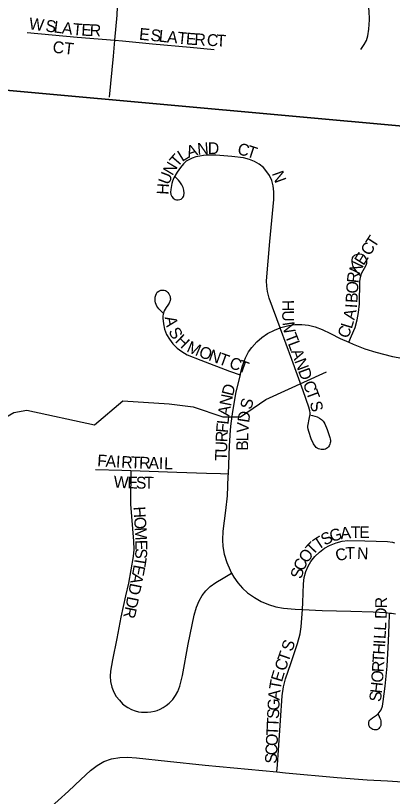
# Model space of a CAD drawing. Extents: x 1410790 to 1770854, y 448063 to 770588.
# Drawn here: x 1547506 to 1549100, y 630526 to 633827 of the extents above; entities that cross this region are included whole.
import ezdxf

# ---------------------------------------------------------------- set-up
doc = ezdxf.new("R2010")
doc.units = 0
for name, color, linetype in [('GM_X_Minor_River', 7, 'Continuous'), ('GM_X_Section', 7, 'Continuous'), ('GM_X_Township_Road', 7, 'Continuous'), ('GM_X_Township_Subdivision', 7, 'Continuous'), ('GM_X_Township_Subdivision_Text', 7, 'Continuous')]:
    doc.layers.add(name, color=color, linetype=linetype)

msp = doc.modelspace()

# ---------------------------------------------------------------- linework, layer by layer
at = {"layer": 'GM_X_Minor_River'}
msp.add_lwpolyline([(1546608.2, 631388.7), (1546727.1, 631426.8), (1546785.1, 631417.8), (1546896.2, 631466), (1547159.2, 631726.2), (1547279.9, 631984.7), (1547319, 632044.2), (1547499.2, 632149.4), (1547553.5, 632158.5), (1547839.2, 632097.4), (1547959.1, 632197.7), (1548155.4, 632186.3), (1548257.4, 632172.5), (1548383, 632130.2), (1548457.2, 632131), (1548564.7, 632203.3), (1548821.3, 632321.2)], dxfattribs=at)
at = {"layer": 'GM_X_Section'}
for points in [[(1550230.3, 638666.5), (1549719.6, 633308.3), (1544399.7, 633789.9), (1544904.4, 639125.6)], [(1544399.7, 633789.9), (1549719.6, 633308.3), (1549189.3, 627980.4), (1543911.7, 628488)]]:
    msp.add_lwpolyline(points, close=True, dxfattribs=at)
at = {"layer": 'GM_X_Township_Road'}
for points in [[(1547505.6, 630342.1), (1547524.9, 630360), (1547546.2, 630380.2), (1547580.6, 630410.5), (1547602.1, 630430.6), (1547642.4, 630468.5), (1547729.7, 630547.9), (1547782.4, 630597.3), (1547823.6, 630634.5), (1547851.7, 630656.2), (1547878.9, 630672.7), (1547912, 630684.4), (1547946.9, 630689.8), (1547979.2, 630691.2), (1548018.2, 630688.7), (1548148.5, 630674.8), (1548308.5, 630657.9), (1548550.2, 630634.8), (1548610.9, 630629.1)], [(1548610.9, 630629.1), (1548648.1, 630625.6), (1548865.9, 630605.1), (1548992.9, 630596.1), (1549079.3, 630590.8), (1549183.8, 630584.4), (1549297.3, 630578.1), (1549312.4, 630577.3)]]:
    msp.add_lwpolyline(points, dxfattribs=at)
at = {"layer": 'GM_X_Township_Subdivision'}
for points in [[(1547926.1, 633723.2), (1547935.6, 633828.9), (1547936.7, 633864.9), (1547934.6, 633900.9), (1547927.8, 633942.9), (1547902.1, 634064.9), (1547875.4, 634196.6), (1547835.2, 634385.9), (1547815.9, 634475.6), (1547805.7, 634537), (1547799.7, 634592.3), (1547798, 634638.1), (1547799.7, 634683.9), (1547806.6, 634749.1), (1547809.7, 634776.1)], [(1548965.9, 633683.3), (1548980.5, 633705.1), (1548989.7, 633722.4), (1548995.6, 633741.1), (1549000.2, 633770.2), (1549002.3, 633809.4), (1549000.9, 633848.7), (1548996.2, 633881.1), (1548987.9, 633912.8), (1548977.2, 633940.3), (1548962, 633969.2), (1548820.5, 634189.7), (1548744.1, 634308), (1548655.5, 634449.6), (1548638.3, 634481.3), (1548628.4, 634505.6), (1548621.4, 634530.8), (1548617.1, 634559.9), (1548616.2, 634595.9), (1548621, 634667.9), (1548623.3, 634703.7)], [(1547555.2, 633755.5), (1547767.2, 633735.9), (1547926.1, 633723.2)], [(1547903.7, 633482.8), (1547920.1, 633655.8), (1547926.1, 633723.2)], [(1547926.1, 633723.2), (1547958, 633720.2), (1548084.8, 633708.3), (1548244.1, 633693.8), (1548346.5, 633684.6)], [(1548624.7, 632506.7), (1548578.5, 632631.9), (1548570.9, 632660.4), (1548568, 632683.1), (1548567.8, 632706), (1548582, 632872.7), (1548598.4, 633049.1), (1548598.8, 633081.9), (1548595.7, 633108), (1548589.7, 633130.1), (1548580.1, 633150.9), (1548569.2, 633167.3), (1548553.9, 633184.4), (1548536.2, 633199), (1548516.4, 633210.6), (1548495.1, 633219.2), (1548469.7, 633225.4), (1548420.9, 633231.8), (1548353.3, 633236.9), (1548333.4, 633237.1), (1548313.6, 633236.6), (1548300.4, 633235.3), (1548285.5, 633233.4), (1548269, 633229.6), (1548253.5, 633225.1), (1548244, 633220.8), (1548235.4, 633216.2), (1548227.7, 633211.1), (1548216, 633200.7), (1548203.3, 633184.8), (1548189.9, 633165.2), (1548175.7, 633141.4), (1548170.2, 633126.9), (1548167.3, 633117.2), (1548163.7, 633100.7), (1548162.3, 633091.3), (1548161.7, 633080.9), (1548162.9, 633071.2), (1548166.6, 633062.2), (1548172.9, 633054.9), (1548181.3, 633050), (1548187, 633048.3), (1548193.8, 633048.1), (1548200.7, 633049.3), (1548206.8, 633051.7), (1548213.9, 633058.2), (1548216.7, 633062.5), (1548218.2, 633066.8), (1548219.3, 633076.4), (1548217.5, 633089.5), (1548214.2, 633100.6), (1548209.7, 633111), (1548201, 633124.4), (1548194.8, 633132.1), (1548182.7, 633144.2), (1548180.6, 633146.1)], [(1548915.4, 632446), (1548926.6, 632472.8), (1548941.7, 632508.9), (1548951, 632540.2), (1548956.9, 632572.3), (1548959.9, 632608.1), (1548961.4, 632702.7), (1548964.3, 632721.9), (1548969.6, 632737.3), (1548988.3, 632771.7), (1548990, 632776.2), (1548990.9, 632781), (1548991.4, 632786.2), (1548991.1, 632790.8), (1548990, 632796.4), (1548988.5, 632800.1), (1548985.8, 632804.7), (1548983.2, 632808.3), (1548979.6, 632811.7), (1548975.6, 632814.4), (1548970.1, 632817), (1548962, 632818.6), (1548956.3, 632818.5), (1548951.1, 632817.7), (1548946.1, 632816.1), (1548941.4, 632814.1), (1548937.9, 632812.1), (1548935, 632809.9), (1548932.6, 632807.3), (1548930.2, 632802.7), (1548929, 632799.2), (1548928.2, 632795.4), (1548928, 632790.8), (1548928, 632785.9), (1548929, 632778.2), (1548930.8, 632771.6), (1548932.6, 632766.5), (1548935, 632761.5), (1548939.2, 632755.1), (1548945.8, 632746.2), (1548961.4, 632730.4), (1548964.3, 632728)], [(1548129.5, 632570.9), (1548123.9, 632575.5), (1548118.5, 632580.5), (1548112.3, 632586.9), (1548107.4, 632593.2), (1548103.9, 632599.1), (1548101, 632605.5), (1548098.4, 632612.5), (1548097, 632619.6), (1548096.1, 632627.8), (1548096.8, 632636.5), (1548098.9, 632645.2), (1548102, 632652.5), (1548105.6, 632657.7), (1548112.1, 632662.7), (1548120, 632665.6), (1548127.7, 632666.6), (1548134.2, 632666.1), (1548140.5, 632664.3), (1548145, 632661.7), (1548149.7, 632656.7), (1548154, 632651.1), (1548157.1, 632645.5), (1548159.4, 632640), (1548160.2, 632634.4), (1548160.6, 632629.9), (1548159.7, 632622.8), (1548156, 632611.9), (1548150.4, 632602.9), (1548143.2, 632593.4), (1548134.4, 632578.4), (1548130.2, 632565.1), (1548129, 632556.3), (1548128.8, 632547.9), (1548131.1, 632524.2), (1548136.5, 632501.2), (1548144.9, 632479), (1548156.4, 632458.4), (1548170.6, 632439.5), (1548189.7, 632420.5), (1548208.6, 632406.3), (1548232.1, 632393.4), (1548290.2, 632370), (1548410.4, 632323.8), (1548455.8, 632308.5)], [(1548624.7, 632506.7), (1548627.6, 632507.8), (1548661.8, 632517.3), (1548687.1, 632521.1), (1548716, 632521.3), (1548744.7, 632518), (1548772.9, 632511.3), (1548803.3, 632500.4), (1548838.4, 632483.5), (1548879.4, 632462.5), (1548915.4, 632446)], [(1548455.8, 632308.5), (1548465.7, 632346.3), (1548478.4, 632379.5), (1548491.7, 632405.2), (1548504.6, 632423.4), (1548526.1, 632447.4), (1548547.9, 632466.4), (1548571.8, 632482.7), (1548600.4, 632497.4), (1548624.7, 632506.7)], [(1548754.1, 632138), (1548761.6, 632136.4), (1548771.3, 632133.9), (1548781.5, 632130.3), (1548790.9, 632124.7), (1548799.4, 632119.3), (1548806.4, 632112.4), (1548809.9, 632107.7), (1548813.6, 632101.5), (1548823.8, 632077.4), (1548835.3, 632042.9), (1548836.8, 632037.1), (1548837.3, 632029.9), (1548837.5, 632025.5), (1548836.6, 632020.2), (1548835.6, 632014.6), (1548832.4, 632008.7), (1548829, 632003.7), (1548825.2, 631999.5), (1548820.5, 631996.9), (1548816.4, 631994.4), (1548811.5, 631993.1), (1548805.5, 631992), (1548798.4, 631992.3), (1548792.1, 631993.7), (1548787.3, 631995.4), (1548781.9, 631997.9), (1548777.6, 632001), (1548772.7, 632006.6), (1548765.9, 632017.2), (1548756.4, 632038.2), (1548745.6, 632069.3), (1548743.4, 632078.1), (1548742.7, 632085.3), (1548742.2, 632091.7), (1548742.8, 632098.3), (1548747.6, 632120.8), (1548750.7, 632134.9), (1548751.3, 632140), (1548751.6, 632148.2), (1548750.6, 632156.3), (1548746.9, 632172.2), (1548722.4, 632240.1), (1548673.7, 632372.5), (1548626.3, 632502.1), (1548624.7, 632506.7)], [(1548915.4, 632446), (1548933.4, 632437.7), (1548982.6, 632418.5), (1549029.9, 632403.9), (1549100.3, 632386.2), (1549155.3, 632375.7), (1549280.4, 632354.9)], [(1548455.8, 632308.5), (1548438.1, 632235.8), (1548423.2, 632153.9), (1548416.9, 632101.8), (1548413.4, 632075.8), (1548409, 632007), (1548404.6, 631889.2)], [(1547844.4, 631907.6), (1547956, 631905.5), (1547993.5, 631904.2)], [(1547993.5, 631904.2), (1547992.9, 631873.1), (1547991.5, 631804.2), (1547991.6, 631761.3), (1548005.5, 631604.6), (1548005.9, 631569), (1548003.1, 631540.2), (1547983.2, 631427.8), (1547970.3, 631373.4), (1547951.8, 631283.4), (1547933.8, 631193.5), (1547915.8, 631103.6), (1547906.9, 631054.8), (1547905.6, 631034.6), (1547907.5, 631011), (1547913, 630988), (1547921.8, 630966), (1547932.1, 630948.3), (1547945, 630932.5), (1547958.6, 630917.6), (1547969.2, 630909.1), (1547981.3, 630901.4), (1547996.9, 630893), (1548012.4, 630887.2), (1548025.8, 630883.6), (1548038.1, 630881.8), (1548051.9, 630881.4), (1548063.6, 630881.3), (1548077.5, 630882.8), (1548093.8, 630885.8), (1548105.4, 630889.4), (1548116.9, 630894.4), (1548130.2, 630901.4), (1548143.4, 630910.2), (1548155.9, 630920.1), (1548170.5, 630935.5), (1548182.8, 630951.8), (1548192.5, 630969.8), (1548200.7, 630991.9), (1548211.6, 631037), (1548236.6, 631169.6), (1548261.7, 631291.7), (1548271.1, 631326), (1548282.3, 631352.7), (1548295.2, 631374.9), (1548310.9, 631395), (1548329.2, 631412.9), (1548352.4, 631430.2), (1548383.4, 631448.1), (1548419.8, 631469.1)], [(1547993.5, 631904.2), (1548188.6, 631897.3), (1548313.1, 631892.8), (1548372.1, 631890.5), (1548404.6, 631889.2)], [(1548404.6, 631889.2), (1548404.3, 631879.1), (1548400.7, 631797.2), (1548393.9, 631735.2), (1548382.6, 631647.3), (1548381, 631611.2), (1548382.8, 631581.7), (1548388.6, 631549.4), (1548398.9, 631514.8), (1548412.9, 631481.6), (1548419.8, 631469.1)], [(1548719.1, 631315.8), (1548720.2, 631345.4), (1548723.3, 631424.4), (1548727, 631451), (1548734, 631477), (1548743.3, 631498.8), (1548755.3, 631519.1), (1548772, 631540.3), (1548791.3, 631559.1), (1548812.8, 631575.4), (1548833.4, 631586.8), (1548861.5, 631597.9), (1548887.6, 631604.8), (1548911.1, 631607.6), (1548983.7, 631606.3), (1549079.3, 631603.4), (1549099.4, 631600.7), (1549108, 631598.4)], [(1548419.8, 631469.1), (1548428.8, 631452.9), (1548445.7, 631428.7), (1548465.3, 631406.5), (1548487.4, 631387), (1548516.9, 631366.1), (1548545.3, 631349.8), (1548575.4, 631336.6), (1548606.7, 631327.1), (1548639, 631321.1), (1548688, 631317.1), (1548719.1, 631315.8)], [(1548610.9, 630629.1), (1548613.3, 630659.7), (1548618.2, 630721.8), (1548626.6, 630845.9), (1548634.2, 630950.2), (1548639.6, 630988.6), (1548648.1, 631023.2), (1548669.7, 631088.1), (1548698.6, 631172), (1548709.8, 631213.5), (1548714.4, 631243.1), (1548719.1, 631315.8)], [(1548719.1, 631315.8), (1548802.7, 631312.4), (1548924, 631309.1), (1549018.9, 631306.3), (1549070.4, 631302.7), (1549088.2, 631300.8)], [(1549039.7, 630873.7), (1549044, 630863.8), (1549047.2, 630856.3), (1549048.9, 630850.5), (1549050.2, 630845.3), (1549051.1, 630836), (1549050.8, 630829.7), (1549050.2, 630825.2), (1549048.3, 630820.2), (1549045.8, 630816.4), (1549042.7, 630813.1), (1549039.7, 630810.6), (1549037.1, 630809.1), (1549033.7, 630807.8), (1549029.2, 630807), (1549026.3, 630806.8), (1549022.2, 630807.3), (1549017.4, 630808.6), (1549012.6, 630810.9), (1549008.1, 630814.1), (1549004.7, 630817.3), (1549002.4, 630820.8), (1549001.1, 630823.6), (1549000, 630826.6), (1548999.4, 630831), (1548999.4, 630835.2), (1549000.2, 630841.2), (1549001.2, 630844.2), (1549003, 630847.5), (1549005.2, 630850.1), (1549008, 630852.5), (1549015.4, 630857.9), (1549032.3, 630869.6), (1549039.4, 630875.2), (1549044.2, 630880.8), (1549051.5, 630891.7), (1549057.5, 630906.9), (1549061.2, 630926.3), (1549068.9, 630991.7), (1549077.8, 631076.6), (1549083.1, 631181.6), (1549086.1, 631252.7), (1549088, 631294.6), (1549088.2, 631300.8)], [(1549088.2, 631300.8), (1549095.9, 631300), (1549112.5, 631298)]]:
    msp.add_lwpolyline(points, dxfattribs=at)

# ---------------------------------------------------------------- texts
at = {"layer": 'GM_X_Township_Subdivision_Text'}
for s, rotation, p in [('W', 352.7686, (1547560.6, 633769.7)), ('S', 352.769, (1547630.5, 633760.8)), ('L', 352.769, (1547665.4, 633756.4)), ('A', 352.7678, (1547700.3, 633751.9)), ('T', 354.7574, (1547745.8, 633746.2)), ('E', 357.2145, (1547783.2, 633742.8)), ('R', 357.5104, (1547818.7, 633741.1)), ('E', 354.3084, (1548026.8, 633725.7)), ('S', 354.3253, (1548074.9, 633720.9)), ('L', 354.3084, (1548110, 633717.4)), ('A', 354.3068, (1548145, 633713.9)), ('T', 354.3084, (1548188.8, 633709.6)), ('E', 355.3171, (1548224.8, 633706)), ('R', 356.6654, (1548261.1, 633703)), ('C', 356.8202, (1548314, 633700)), ('T', 356.8357, (1548353.5, 633697.8)), ('CT', 353.6625, (1547661, 633671)), ('A', 18.276, (1548237.5, 633225)), ('N', 4.5077, (1548276.2, 633238.1)), ('D', 0.306, (1548319.1, 633241.5)), ('C', 346.5411, (1548441.4, 633241.6)), ('T', 342.17, (1548479, 633232.6)), ('T', 49.292, (1548190.5, 633183.7)), ('L', 31.6057, (1548210.3, 633207.8)), ('N', 59.1, (1548169.2, 633147.8)), ('N', 289.8038, (1548589.3, 633160.2)), ('U', 69.2214, (1548154.6, 633108.8)), ('H', 86.545, (1548152.8, 633068.8)), ('T', 57.1663, (1549024.9, 632841.6)), ('C', 57.176, (1549003.4, 632808.3)), ('E', 57.424, (1548977.3, 632767.6)), ('N', 64.6081, (1548959.3, 632729.3)), ('R', 83.8448, (1548956.2, 632694.2)), ('O', 86.5473, (1548953.6, 632650.9)), ('B', 86.2812, (1548951.1, 632611.1)), ('H', 270.2405, (1548633.7, 632625.1)), ('A', 77.2953, (1548938.8, 632537.6)), ('I', 86.4608, (1548949.7, 632589.2)), ('A', 281.1728, (1548136.4, 632551.5)), ('U', 270.252, (1548633.8, 632581.1)), ('N', 278.4095, (1548634.6, 632529.3)), ('C', 67.892, (1548911, 632458.7)), ('L', 73.1987, (1548927.6, 632500.2)), ('S', 299.2804, (1548150.9, 632492.2)), ('H', 316.1625, (1548177.9, 632448.8)), ('T', 291.2727, (1548644.2, 632474)), ('M', 336.9329, (1548226.1, 632407.5)), ('L', 290.4313, (1548656.9, 632441.4)), ('O', 340.0333, (1548277.4, 632385.7)), ('N', 340.0903, (1548318.8, 632370.7)), ('T', 340.0706, (1548360.2, 632355.7)), ('C', 340.0957, (1548405.7, 632339.2)), ('A', 290.4051, (1548669.2, 632408.4)), ('N', 290.4232, (1548684.5, 632367.2)), ('T', 340.1253, (1548442.9, 632325.7)), ('D', 290.4051, (1548699.9, 632325.9)), ('C', 290.4168, (1548719.8, 632272.3)), ('D', 76.2765, (1548425.4, 632216.1)), ('T', 290.4251, (1548733.7, 632235.2)), ('N', 78.4029, (1548416.6, 632173.5)), ('S', 75.5331, (1548502.7, 632158.9)), ('S', 283.6785, (1548749.7, 632191.1)), ('A', 81.1342, (1548410, 632130.7)), ('D', 81.2887, (1548493.3, 632103.8)), ('L', 83.702, (1548406.2, 632096.3)), ('F', 85.2681, (1548403.3, 632061.6)), ('V', 85.8209, (1548490.2, 632061)), ('R', 87.9355, (1548401.9, 632022.6)), ('L', 89.0711, (1548489.7, 632026.5)), ('U', 88.0326, (1548400.4, 631978.6)), ('B', 89.9271, (1548489.6, 631987.1)), ('T', 88.0599, (1548399.2, 631943.5)), ('F', 356.5549, (1547850.4, 631921.8)), ('A', 356.545, (1547885.5, 631919.6)), ('I', 356.5437, (1547929.5, 631917)), ('R', 356.8075, (1547951.7, 631915.6)), ('T', 358.0217, (1547992.4, 631913.4)), ('R', 358.5449, (1548028, 631912.1)), ('A', 358.5741, (1548067.7, 631911.1)), ('I', 358.557, (1548111.6, 631910.1)), ('L', 358.5746, (1548133.7, 631909.5)), ('W', 356.9218, (1547920, 631831.5)), ('E', 358.4501, (1547978.5, 631828.4)), ('S', 359.3543, (1548014.6, 631827.4)), ('T', 359.9208, (1548050.3, 631827)), ('H', 273.3459, (1548004.4, 631750.2)), ('O', 273.3241, (1548007, 631706.2)), ('M', 273.3318, (1548009.5, 631662.3)), ('G', 16.8311, (1548842.2, 631600.8)), ('A', 5.9781, (1548881.8, 631613.1)), ('T', 0.9289, (1548924.4, 631617.6)), ('E', 0, (1548959.4, 631618.2)), ('T', 33.1521, (1548785.4, 631566)), ('S', 29.1077, (1548814, 631584.8)), ('E', 270.9835, (1548012.6, 631610.1)), ('T', 46.4104, (1548763.4, 631542.5)), ('S', 267.978, (1548013.2, 631575.6)), ('O', 53.4536, (1548738.3, 631508.4)), ('C', 18.2507, (1548867.9, 631517.5)), ('T', 1.6124, (1548901.8, 631529.3)), ('N', 357.6823, (1548949.3, 631529.7)), ('T', 261.0586, (1548012.1, 631542)), ('C', 66.3581, (1548723.9, 631474.7)), ('E', 258.9473, (1548006.7, 631507.7)), ('S', 75.2217, (1548715.6, 631442.6)), ('A', 258.3557, (1548000, 631473.3)), ('D', 258.3601, (1547991.1, 631430.2)), ('D', 258.3596, (1547979.6, 631374.2)), ('R', 89.9466, (1549076.8, 631320.9)), ('R', 258.3615, (1547970.7, 631331.1)), ('D', 88.3376, (1549075.5, 631275.3)), ('L', 86.7083, (1549072.6, 631225.4)), ('L', 86.6977, (1549070.6, 631190.3)), ('S', 70.8484, (1548675.4, 631135.5)), ('H', 86.6977, (1549066.8, 631124.3)), ('I', 86.6772, (1549069.3, 631168.3)), ('T', 70.8479, (1548659.5, 631089.7)), ('T', 86.7083, (1549064.8, 631089.2)), ('C', 70.8968, (1548646.5, 631052.3)), ('R', 86.6891, (1549062.5, 631049.7)), ('E', 73.3191, (1548632.3, 631006.7)), ('O', 86.3898, (1549059.7, 631005.5)), ('T', 79.9762, (1548626.6, 630973.5)), ('H', 83.9991, (1549054.9, 630959.4)), ('A', 85.142, (1548623, 630930.8)), ('S', 82.9597, (1549050.5, 630923.5)), ('G', 87.3132, (1548621, 630887.4)), ('S', 87.2945, (1548619.3, 630852.2)), ('T', 87.3218, (1548617.6, 630817)), ('T', 87.3278, (1548616, 630781.9)), ('O', 87.3111, (1548613.9, 630737.9)), ('C', 87.3037, (1548612.1, 630698.3)), ('S', 87.3218, (1548610.4, 630663.2))]:
    msp.add_text(s, height=50, rotation=rotation, dxfattribs=at).set_placement(p)

doc.saveas('drawing.dxf')
